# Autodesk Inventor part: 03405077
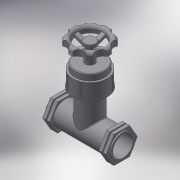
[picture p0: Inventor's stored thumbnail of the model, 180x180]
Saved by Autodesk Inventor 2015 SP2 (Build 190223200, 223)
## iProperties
Created: 2017-05
Part Number: 03405077
Material: Generic
Description: PLASSON THREADED STOPTAP 3/4"
Document SubType Name: Modeling
Designer: KIM
Mass: 78.2644 g
Surface Area: 269.076 cm^2
Volume: 78.2644 cm^3
Density: 1 g/cm^3
Appearance: Default
Author: KIM
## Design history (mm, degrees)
derived "03405.ipt"
feature "Solid1::03405.ipt"
tag "TaggingFeature1"
body "Solid1"
other parameters: "d13" = 13.5, "d17" = 35.88, "d19" = 59.8, "d22" = 27.6, "d23" = 18.4, "d24" = 41.4, "d25" = 11.04, "d26" = 90 deg, "d27" = 32.2, "d28" = 70 deg, "d29" = 13.8, "d30" = 11.04, "d31" = 13.8, "d32" = 46, "d33" = 32.2, "d36" = 92, "d41" = 1, "d43" = 2.76, "d44" = 2.76, "d46" = 0, "d48" = 360 deg, "d50" = 0.46, "d51" = 0.46, "d53" = 360 deg, "d69" = 39.1, "d70" = 2.76, "d71" = 2.76, "d72" = 5.52, "d74" = 0, "d75" = 0.46, "d77" = 360 deg, "d80" = 40.158, "d81" = 13.8, "d82" = 6.9, "d83" = 16.56, "d84" = 0, "d86" = 360 deg, "d88" = 0.92, "d89" = 7.36, "d90" = 24.117, "d91" = 78, "d92" = 18, "d93" = 32, "d94" = 28.9404, "d95" = 3.6, "d96" = 1.44, "d97" = 21.7053, "d100" = 0, "d104" = 0, "d106" = 0, "d107" = 0.92, "d108" = 0.644, "d111" = 92, "H_" = 78, "R_" = 24.117, "l_2" = 18, "A_" = 92, "d67" = 46, "d68" = 32.2, "d79" = 41.4
